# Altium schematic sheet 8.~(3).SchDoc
size 420 x 297 mm
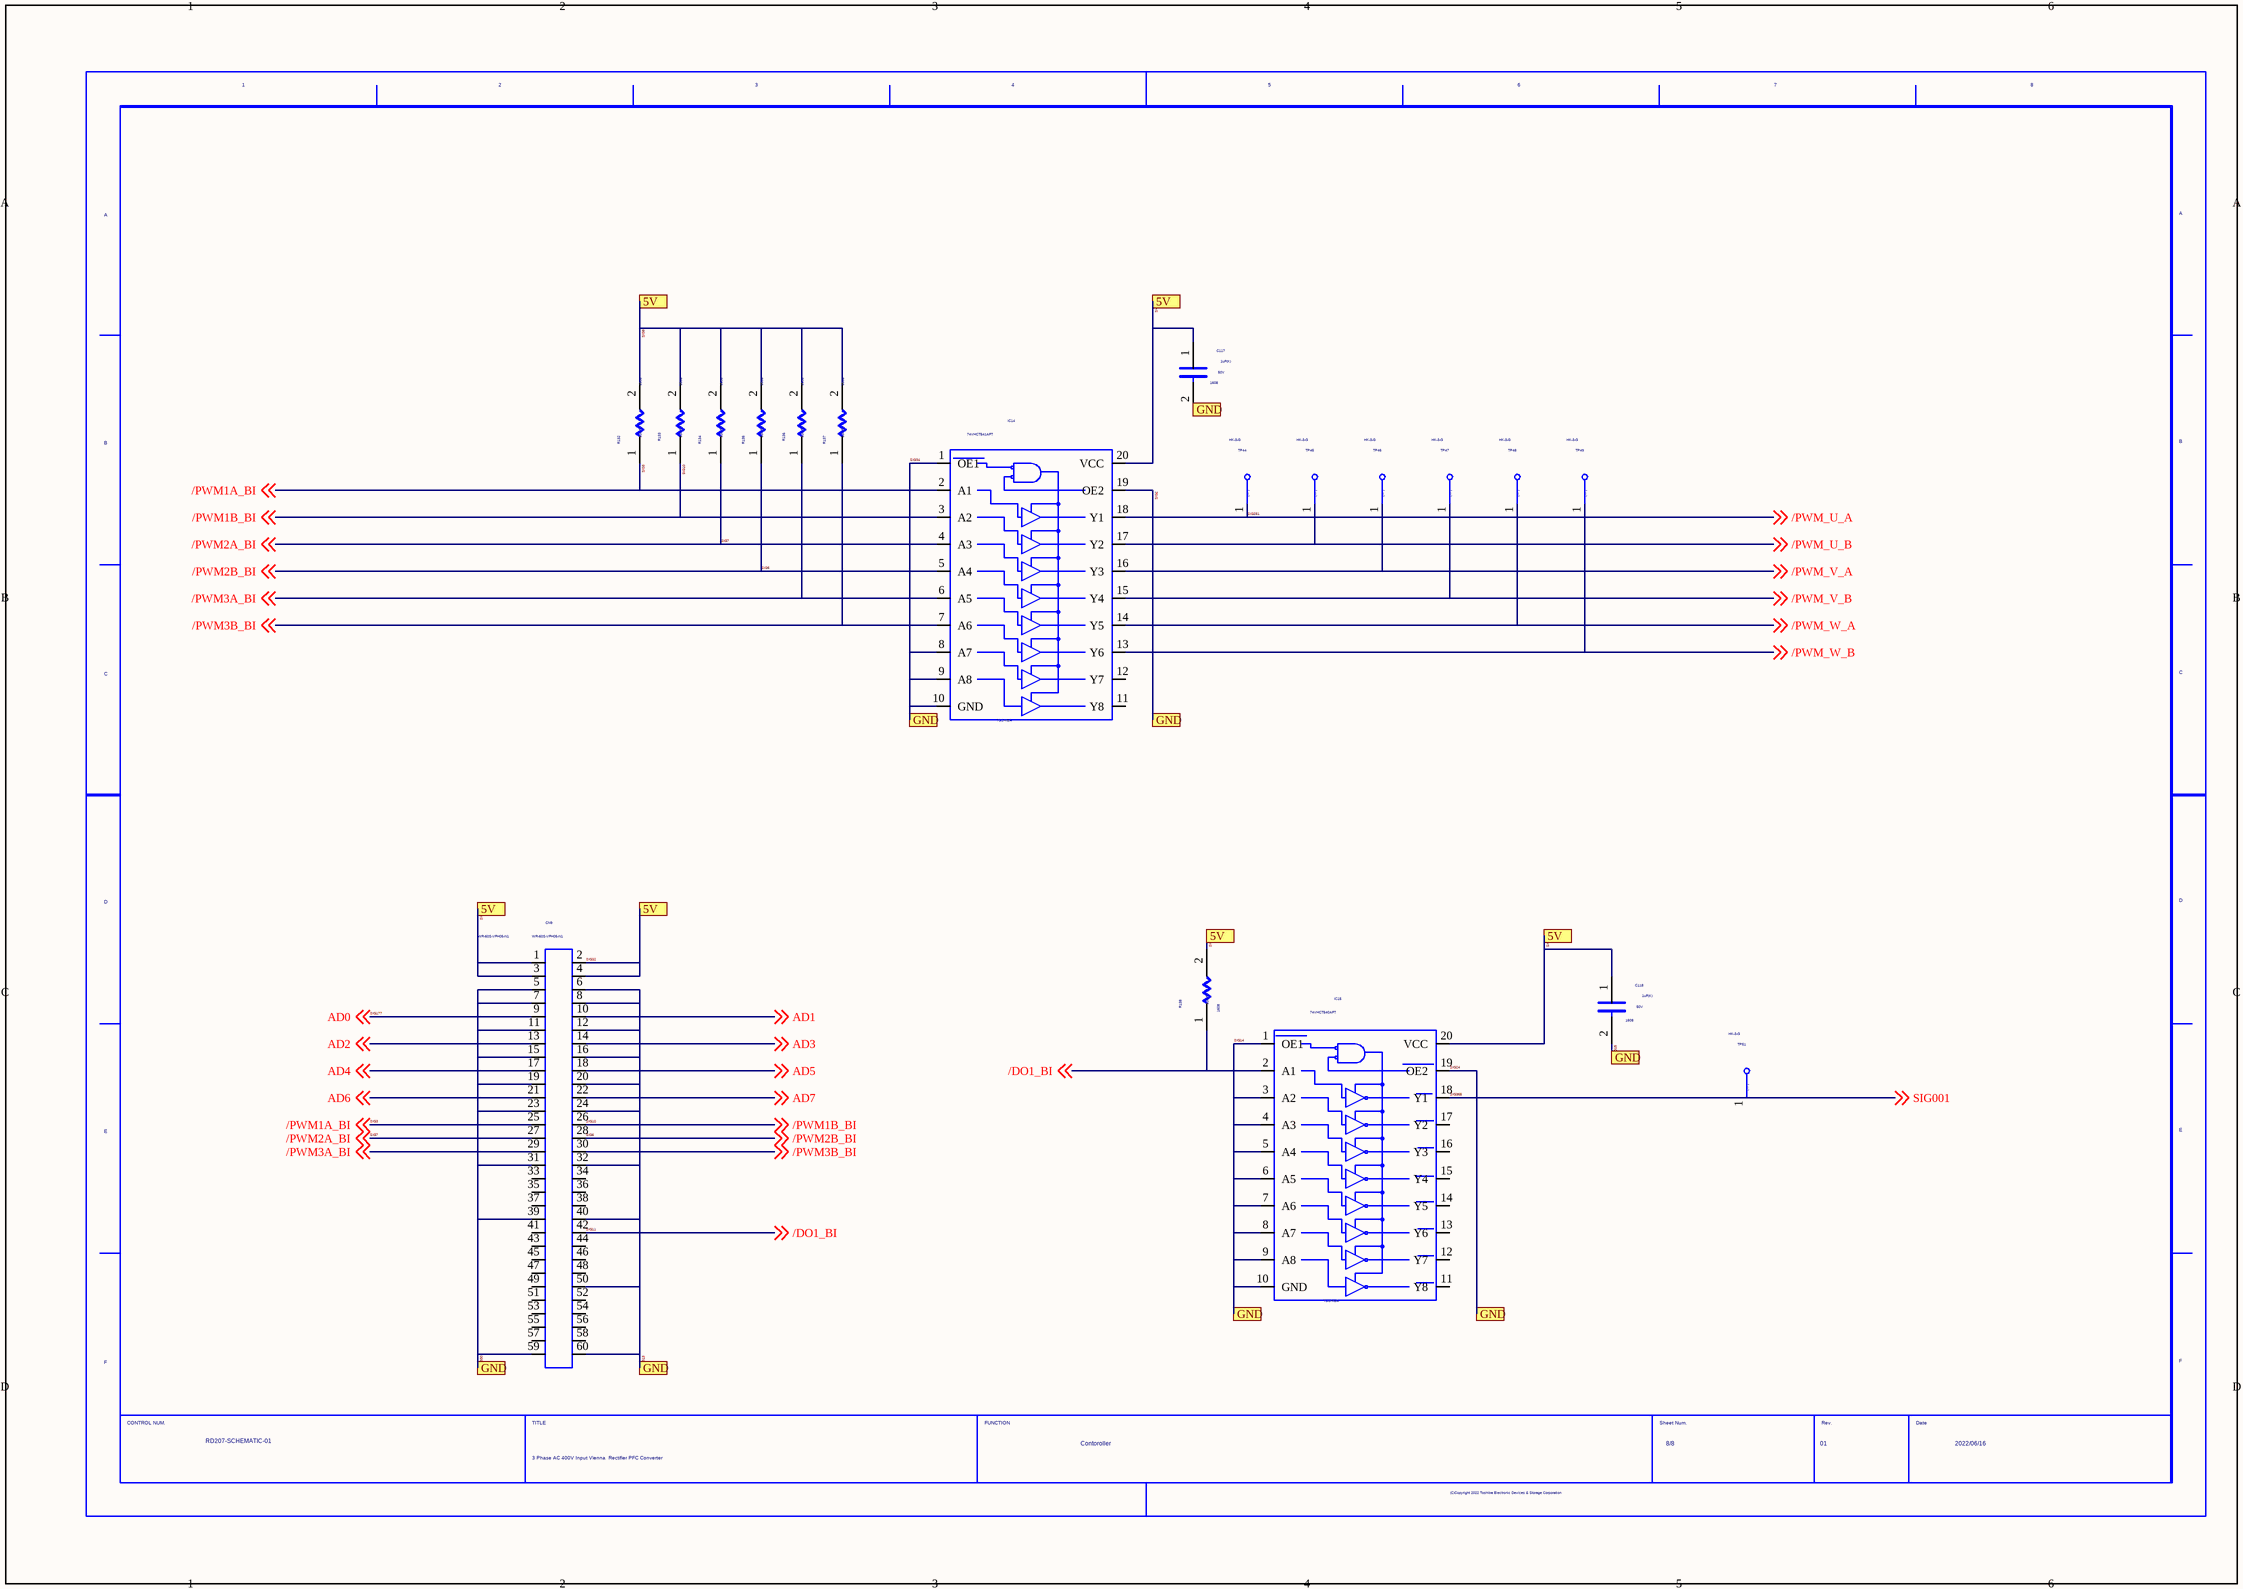
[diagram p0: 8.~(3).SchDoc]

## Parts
C117  SIZECODESMD: 1608  VAL2: 50V  VAL1: 1uF(K)  (hidden comment: C)
C118  SIZECODESMD: 1608  VAL2: 50V  VAL1: 1uF(K)  (hidden comment: C)
CN9  WR-60S-VFH05-N1
IC14  USERCOMPTEXT3: TOSHIBA  VAL3: 74VHCT541AFT  (hidden comment: 74VHC541FT)
IC15  USERCOMPTEXT3: TOSHIBA  VAL3: 74VHCT540AFT  (hidden comment: 74VHC540FT)
R132  SIZECODESMD: 1608  VAL1: 10k(F)  (hidden comment: R)
R133  SIZECODESMD: 1608  VAL1: 10k(F)  (hidden comment: R)
R134  SIZECODESMD: 1608  VAL1: 10k(F)  (hidden comment: R)
R135  SIZECODESMD: 1608  VAL1: 10k(F)  (hidden comment: R)
R136  SIZECODESMD: 1608  VAL1: 10k(F)  (hidden comment: R)
R137  SIZECODESMD: 1608  VAL1: 10k(F)  (hidden comment: R)
R138  SIZECODESMD: 1608  VAL1: 10k(F)  (hidden comment: R)
TP44  VAL3: HK-3-G  (hidden comment: TP)
TP45  VAL3: HK-3-G  (hidden comment: TP)
TP46  VAL3: HK-3-G  (hidden comment: TP)
TP47  VAL3: HK-3-G  (hidden comment: TP)
TP48  VAL3: HK-3-G  (hidden comment: TP)
TP49  VAL3: HK-3-G  (hidden comment: TP)
TP51  VAL3: HK-3-G  (hidden comment: TP)
U?  DATE: 2022/06/16  TITLE: 3 Phase AC 400V Input Vienna / Rectifier PFC Converter  REVISION: 01  SHEETNUMBER: 8/8  FUNCTION: Contoroller  DRAWINGNUMBER: RD207-SCHEMATIC-01  (hidden comment: WAKU_DEF100)

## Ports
5V, GND

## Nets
/PWM3A_BI: CN9.29 IC14.6(A5) R136.1 ; off-sheet /PWM3A_BI
/PWM3B_BI: CN9.30 IC14.7(A6) R137.1 ; off-sheet /PWM3B_BI
/PWM_U_B: IC14.17(Y2) TP45.1 ; off-sheet /PWM_U_B
/PWM_V_A: IC14.16(Y3) TP46.1 ; off-sheet /PWM_V_A
/PWM_V_B: IC14.15(Y4) TP47.1 ; off-sheet /PWM_V_B
/PWM_W_A: IC14.14(Y5) TP48.1 ; off-sheet /PWM_W_A
/PWM_W_B: IC14.13(Y6) TP49.1 ; off-sheet /PWM_W_B
AD1: CN9.10 ; off-sheet AD1
AD2: CN9.13 ; off-sheet AD2
AD3: CN9.14 ; off-sheet AD3
AD4: CN9.17 ; off-sheet AD4
AD5: CN9.18 ; off-sheet AD5
AD6: CN9.21 ; off-sheet AD6
AD7: CN9.22 ; off-sheet AD7
SIG3: CN9.25 IC14.2(A1) R132.1 ; off-sheet /PWM1A_BI  [also labelled /PWM1A_BI]
SIG6: CN9.28 IC14.5(A4) R135.1 ; off-sheet /PWM2B_BI  [also labelled /PWM2B_BI]
SIG7: CN9.27 IC14.4(A3) R134.1 ; off-sheet /PWM2A_BI  [also labelled /PWM2A_BI]
SIG10: CN9.26 IC14.3(A2) R133.1 ; off-sheet /PWM1B_BI  [also labelled /PWM1B_BI]
SIG11: CN9.42 IC15.2(A1) R138.1 ; off-sheet /DO1_BI  [also labelled /DO1_BI]
SIG13: C117.2 C118.2 CN9.5 CN9.6 CN9.7 CN9.8 CN9.11 CN9.12 CN9.15 CN9.16 CN9.19 CN9.20 CN9.23 CN9.24 CN9.31 CN9.32 CN9.39 CN9.40 CN9.50 CN9.59 CN9.60 IC14.1(OE1) IC14.8(A7) IC14.9(A8) IC14.10(GND) IC14.19(OE2) IC15.1(OE1) IC15.3(A2) IC15.4(A3) IC15.5(A4) IC15.6(A5) IC15.7(A6) IC15.8(A7) IC15.9(A8) IC15.10(GND) IC15.19(OE2) ; port GND  [also labelled SIG14, SIG15, SIG2, SIG24, SIG30, SIG34]
SIG17: C117.1 C118.1 CN9.1 CN9.2 CN9.3 CN9.4 IC14.20(VCC) IC15.20(VCC) R132.2 R133.2 R134.2 R135.2 R136.2 R137.2 R138.2 ; port 5V  [also labelled SIG19, SIG25, SIG32, SIG33, SIG9]
SIG177: CN9.9 ; off-sheet AD0  [also labelled AD0]
SIG281: IC14.18(Y1) TP44.1 ; off-sheet /PWM_U_A  [also labelled /PWM_U_A]
SIG365: IC15.18(Y1) TP51.1 ; off-sheet SIG001  [also labelled SIG001]

Not connected (* = marked no-connect by the designer): CN9 33 34 35 36 37 38 41 43 44 45 46 47 48 49 51 52 53 54 55 56 57 58; IC14 11(Y8) 12(Y7); IC15 11(Y8) 12(Y7) 13(Y6) 14(Y5) 15(Y4) 16(Y3) 17(Y2)

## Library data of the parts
C117 C118 = C: OriginalSymbolOrigin: (2540,7620); COMP: -C-UMK107AB7105KA-T
CN9 = WR_60S_VFH05_N1: Terminal, 200V, 0.3A; MANUFACTURER: JAE; COMP: -CN-WR-60S-VFH05-N1; NOTE: 60pin; TIME: 16:53:54; UPDATEUSER: t5459927; UPDATETIME: 14:46:38; SAVECOUNT: 2; SAVEAREA0: -56595,-80318,58967,4405; OriginalSymbolOrigin: (0,0)
IC14 = 74VHC541FT_0: Buffer; COMP: -IC-74VHCT541AFT; TIME: 16:53:58; UPDATEUSER: t5459927; UPDATETIME: 14:50:23; SAVECOUNT: 2; SAVEAREA0: -22847,-24597,51708,30063; OriginalSymbolOrigin: (0,0)
IC15 = 74VHC540FT: Buffer; COMP: -IC-74VHCT540AFT; TIME: 16:53:55; UPDATEUSER: t5459927; UPDATETIME: 14:48:47; SAVECOUNT: 2; SAVEAREA0: -22628,-27657,51926,27001; OriginalSymbolOrigin: (0,0)
R132-R138 = R: OriginalSymbolOrigin: (5080,5080); VAL2: 100mW; COMP: -R-ERJ3EKF1002V
TP44-TP49 TP51 = TP: TIME: 16:12:21; UPDATEUSER: fukuda-y; UPDATETIME: 16:18:11; SAVECOUNT: 2; SAVEAREA0: -242,-92,12810,7836; OriginalSymbolOrigin: (0,7620); COMP: -TP-HK-3-G
U? = WAKU_DEF100: PLOTTIME: HH:MM; SAVEAREA0: 22200,72372,612276,319236; TIME: 14:30:25; UPDATEUSER: t5459927; UPDATETIME: 09:21:33; SAVECOUNT: 7; OriginalSymbolOrigin: (10160,284480)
